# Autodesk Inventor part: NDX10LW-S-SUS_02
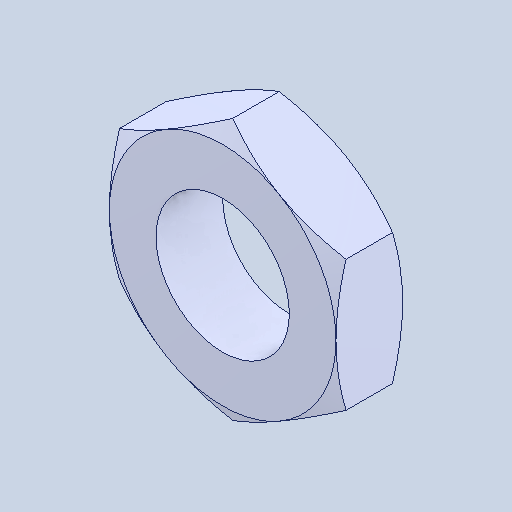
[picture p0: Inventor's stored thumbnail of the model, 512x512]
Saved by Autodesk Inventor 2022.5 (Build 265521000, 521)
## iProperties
Created: 2024-05
Part Number: NDX10LW-S-SUS_02
Material: 一般
Document SubType Name: Modeling
Designer: ImaoCorp
Density: 1 g/cm^3
Appearance: 既定
Author: ImaoCorp
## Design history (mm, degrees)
feature "NDX10LW-S-SUS_02"
node "ソリッド1"
